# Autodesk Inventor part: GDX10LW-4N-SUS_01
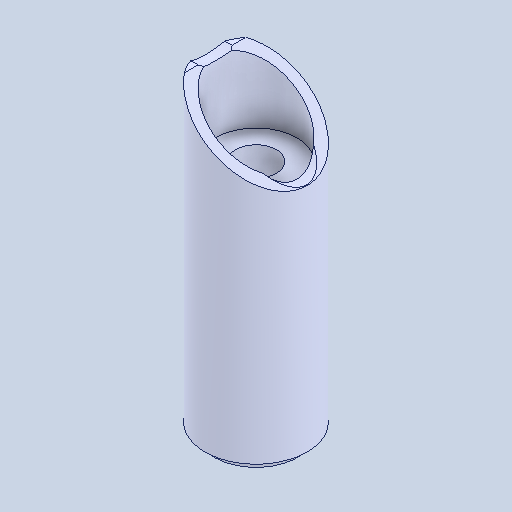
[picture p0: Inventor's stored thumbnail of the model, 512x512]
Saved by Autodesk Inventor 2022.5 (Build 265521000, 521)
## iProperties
Created: 2024-06
Part Number: GDX10LW-4N-SUS_01
Material: 一般
Document SubType Name: Modeling
Designer: ImaoCorp
Density: 1 g/cm^3
Appearance: 既定
Author: ImaoCorp
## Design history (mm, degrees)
feature "GDX10LW-4N-SUS_01"
node "ソリッド1"
